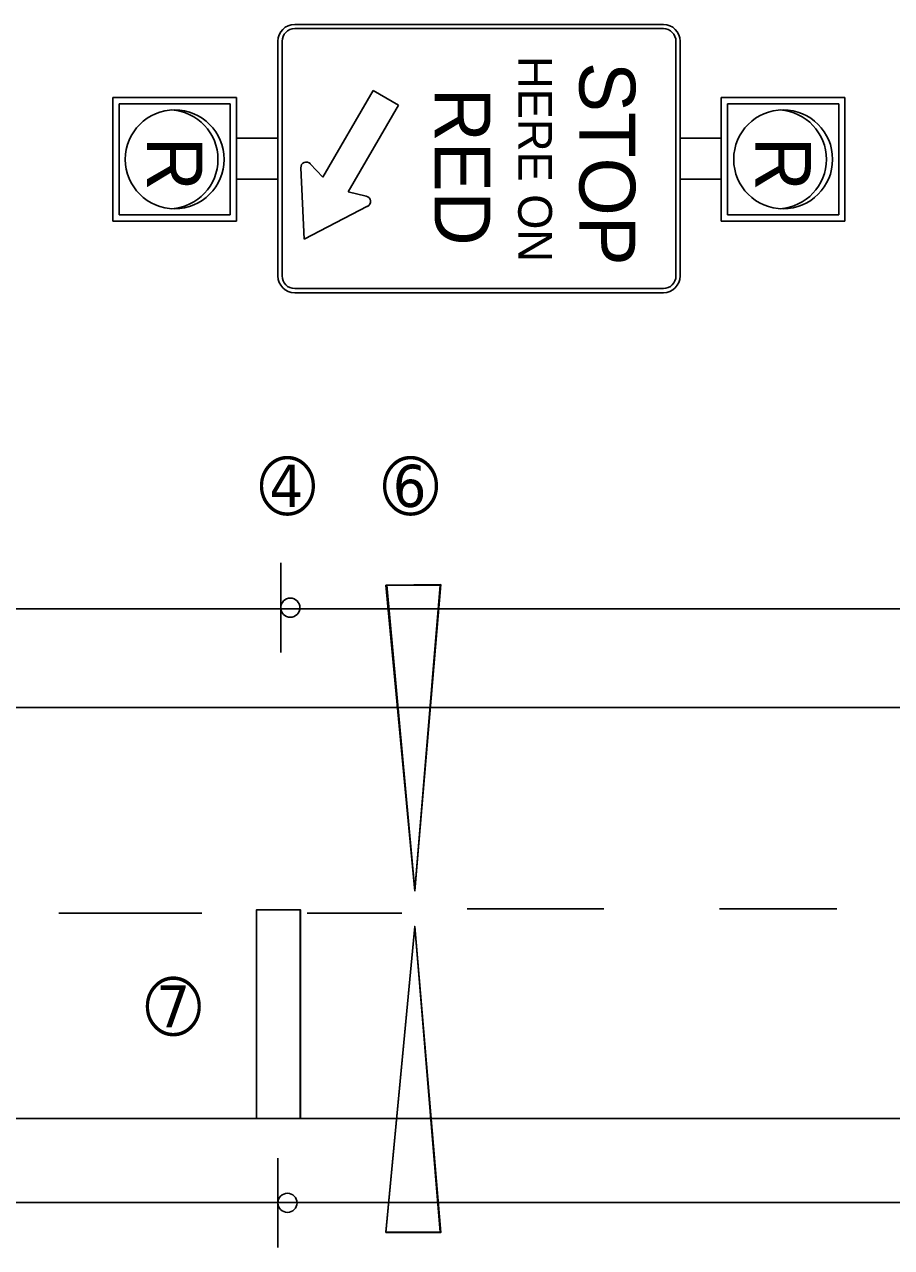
# Model space of a CAD drawing. Extents: x 15 to 764, y 7 to 487.
# Drawn here: x 477.5 to 535.1, y 389.5 to 470.8 of the extents above; entities that cross this region are included whole.
import ezdxf

# ---------------------------------------------------------------- set-up
doc = ezdxf.new("R2010")
doc.units = 0
doc.layers.add('Default', color=7, linetype='Continuous')
doc.layers.add('TextStructures', color=7, linetype='Continuous')

msp = doc.modelspace()

# ---------------------------------------------------------------- linework, layer by layer
at = {"layer": 'Default'}
for p, q in [((519.965, 470.826), (495.443, 470.826)), ((519.965, 470.547), (495.443, 470.547)), ((494.328, 469.711), (494.328, 454.106)), ((494.607, 469.711), (494.607, 454.106)), ((520.801, 454.106), (520.801, 469.711)), ((521.079, 454.106), (521.079, 469.711)), ((483.353, 465.969), (483.353, 457.749)), ((491.573, 465.969), (483.353, 465.969)), ((491.573, 457.749), (491.573, 465.969)), ((497.322, 460.668), (500.656, 466.444)), ((500.656, 466.444), (502.345, 465.468)), ((523.817, 465.97), (523.817, 457.749)), ((532.037, 465.97), (523.817, 465.97)), ((532.037, 457.749), (532.037, 465.97)), ((483.764, 465.558), (483.764, 458.16)), ((491.162, 465.558), (483.764, 465.558)), ((491.162, 458.16), (491.162, 465.558)), ((502.345, 465.468), (499.011, 459.693)), ((524.228, 465.559), (524.228, 458.16)), ((531.626, 465.559), (524.228, 465.559)), ((531.626, 458.16), (531.626, 465.559)), ((491.611, 463.268), (494.328, 463.268)), ((521.079, 463.268), (523.797, 463.268)), ((496.067, 456.544), (495.851, 461.298)), ((496.484, 461.564), (497.322, 460.668)), ((491.611, 460.55), (494.328, 460.55)), ((521.079, 460.55), (523.797, 460.55)), ((499.011, 459.693), (500.206, 459.416)), ((500.292, 458.735), (496.067, 456.544)), ((483.764, 458.16), (491.162, 458.16)), ((524.228, 458.16), (531.626, 458.16)), ((483.353, 457.749), (491.573, 457.749)), ((523.817, 457.749), (532.037, 457.749)), ((495.443, 453.27), (519.965, 453.27)), ((495.443, 452.992), (519.965, 452.992)), ((494.515, 435.023), (494.515, 429.078)), ((501.503, 433.539), (505.115, 433.539)), ((503.433, 413.212), (501.503, 433.539)), ((505.115, 433.539), (501.565, 433.539)), ((505.115, 433.539), (503.433, 413.212)), ((503.438, 413.271), (505.115, 433.539)), ((401.848, 431.975), (746.648, 431.975)), ((401.848, 425.413), (746.648, 425.413)), ((479.748, 411.737), (489.279, 411.737)), ((496.273, 411.737), (502.566, 411.737)), ((506.918, 412.036), (515.996, 412.036)), ((523.693, 412.036), (531.503, 412.036)), ((503.433, 410.859), (501.503, 390.533)), ((505.115, 390.533), (503.433, 410.859)), ((505.115, 390.533), (503.433, 410.859)), ((401.848, 398.094), (746.648, 398.094)), ((495.234, 398.094), (495.816, 398.094)), ((494.324, 395.457), (494.324, 389.513)), ((401.848, 392.502), (746.648, 392.502)), ((501.503, 390.533), (505.115, 390.533))]:
    msp.add_line(p, q, dxfattribs=at)
for points in [[(501.565, 433.539), (505.157, 433.592), (503.437, 413.271)], [(495.83, 398.094), (495.83, 411.969), (492.907, 411.969), (492.907, 398.094)], [(492.91, 411.941), (495.816, 411.969), (495.816, 398.088), (492.91, 398.116)], [(501.513, 390.523), (505.165, 390.523), (503.433, 410.859)]]:
    msp.add_lwpolyline(points, close=True, dxfattribs=at)
for points in [[(501.565, 433.539), (503.437, 413.271)], [(495.816, 398.094), (495.816, 411.969), (492.91, 411.941), (492.91, 398.116)], [(503.433, 410.859), (501.513, 390.523)], [(492.91, 398.116), (495.234, 398.094)], [(501.513, 390.523), (505.115, 390.523)]]:
    msp.add_lwpolyline(points, dxfattribs=at)
for centre, radius in [((487.463, 461.859), 3.288), ((527.927, 461.859), 3.288), ((495.152, 432.051), 0.637), ((494.961, 392.485), 0.637)]:
    msp.add_circle(centre, radius, dxfattribs=at)
for centre, radius, start, end in [((495.443, 469.711), 1.115, 90, 180), ((519.965, 469.711), 1.115, 0, 90), ((495.443, 469.711), 0.836, 90, 180), ((519.965, 469.711), 0.836, 0, 90), ((487.052, 461.859), 3.288, 273.58332, 86.41668), ((527.516, 461.859), 3.288, 273.58332, 86.41668), ((496.217, 461.315), 0.366, 43.05632, 182.59674), ((500.123, 459.059), 0.366, 297.40328, 76.9437), ((495.443, 454.106), 1.115, 180, 270), ((495.443, 454.106), 0.836, 180, 270), ((519.965, 454.106), 1.115, 270, 360), ((519.965, 454.106), 0.836, 270, 360)]:
    msp.add_arc(centre, radius, start, end, dxfattribs=at)

# ---------------------------------------------------------------- texts
for s, height, p in [('HERE ON', 2.2471, (510.31, 468.722)), ('STOP', 3.7182, (514.377, 468.329)), ('RED', 3.7182, (504.746, 466.616))]:
    msp.add_text(s, height=height, rotation=270, dxfattribs=at).set_placement(p)
at = {"layer": 'TextStructures'}
for p in [(485.612, 463.342), (526.076, 463.34)]:
    msp.add_text('R', height=3.699, rotation=270, dxfattribs=at).set_placement(p)
for s, p in [('➃', (493.109, 438.403)), ('➅', (501.298, 438.403)), ('➆', (485.521, 403.797))]:
    msp.add_text(s, height=3.5, dxfattribs=at).set_placement(p)

doc.saveas('drawing.dxf')
